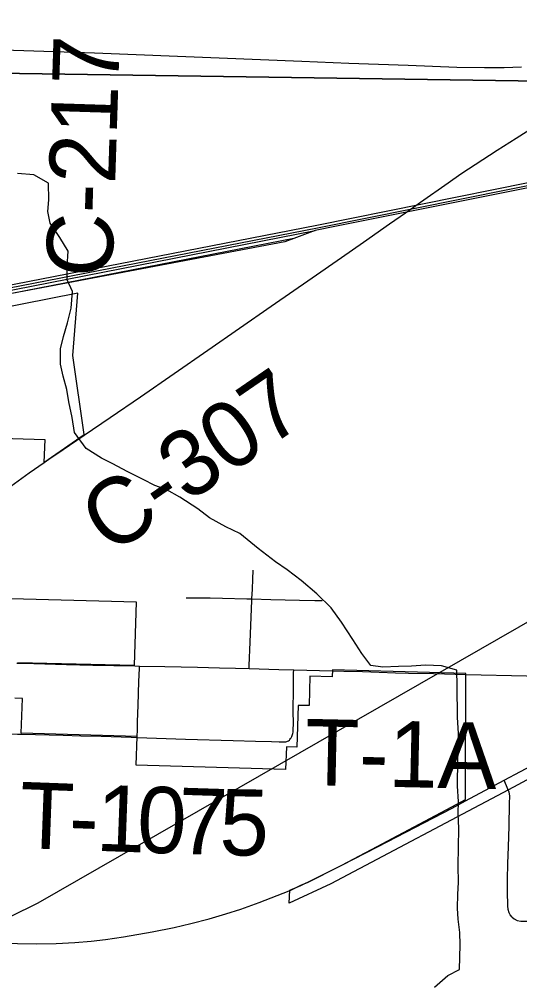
# Model space of a CAD drawing. Extents: x 0 to 34, y 0 to 22.
# Drawn here: x 7.754 to 8.183, y 17.768 to 18.594 of the extents above; entities that cross this region are included whole.
import ezdxf

# ---------------------------------------------------------------- set-up
doc = ezdxf.new("R2010")
doc.units = 0
for name, color, linetype in [('GM_X_City_Street', 7, 'Continuous'), ('GM_X_Corporation', 7, 'Continuous'), ('GM_X_County_Road', 7, 'Continuous'), ('GM_X_County_Road_Text', 7, 'Continuous'), ('GM_X_Minor_River', 7, 'Continuous'), ('GM_X_Rail_Line', 7, 'Continuous'), ('GM_X_State_Route', 7, 'Continuous'), ('GM_X_Township_Road', 7, 'Continuous'), ('GM_X_Township_Road_Text', 7, 'Continuous'), ('GM_X_US_Route', 7, 'Continuous')]:
    doc.layers.add(name, color=color, linetype=linetype)

msp = doc.modelspace()

# ---------------------------------------------------------------- linework, layer by layer
at = {"layer": 'GM_X_City_Street'}
for points in [[(8.17665, 17.82278), (8.175, 17.82467), (8.17417, 17.82649), (8.17328, 17.82943), (8.17286, 17.8325), (8.17261, 17.84493), (8.17277, 17.84885), (8.17272, 17.85509), (8.17305, 17.86874), (8.17364, 17.88324), (8.17404, 17.90092), (8.17452, 17.91992), (8.17459, 17.92691), (8.1741, 17.93021), (8.17311, 17.93259), (8.16992, 17.94028)], [(8.17665, 17.82278), (8.17846, 17.8213), (8.18093, 17.81999), (8.18414, 17.81933), (8.19243, 17.81935), (8.20548, 17.81916), (8.22177, 17.81868), (8.2397, 17.81796), (8.24653, 17.81786), (8.26142, 17.81765), (8.27735, 17.81711), (8.28412, 17.81701)]]:
    msp.add_lwpolyline(points, dxfattribs=at)
at = {"layer": 'GM_X_Corporation'}
for points in [[(8.81843, 19.53953), (8.78463, 18.5318), (7.73457, 18.54715), (7.75042, 19.56547)], [(7.73457, 18.54715), (8.78463, 18.5318), (8.76248, 17.51563), (7.70158, 17.53728)]]:
    msp.add_lwpolyline(points, close=True, dxfattribs=at)
for points in [[(7.72952, 18.23415), (7.77593, 18.23266), (7.7753, 18.21318), (7.80971, 18.23699), (7.8002, 18.30491), (7.8043, 18.35842), (7.73309, 18.34439)], [(7.75292, 18.04149), (7.85301, 18.03916), (7.85462, 18.09328), (7.72505, 18.09663)], [(8.25627, 17.97639), (8.17353, 17.93211), (8.02112, 17.85142), (7.98558, 17.83486), (7.98622, 17.84585), (7.99549, 17.85006), (8.00557, 17.85469), (8.03056, 17.86754), (8.06104, 17.88347), (8.0694, 17.88803), (8.12484, 17.91745), (8.13672, 17.92378), (8.1371, 18.03187), (8.0227, 18.03496), (8.0225, 18.02919), (8.00328, 18.02972), (8.00277, 18.00436), (7.99322, 18.0046), (7.99199, 17.96865), (7.98336, 17.96891), (7.98234, 17.94961), (7.85446, 17.95315), (7.85528, 17.97775), (7.75587, 17.98058), (7.75702, 18.0106), (7.75033, 18.01077)]]:
    msp.add_lwpolyline(points, dxfattribs=at)
at = {"layer": 'GM_X_County_Road'}
for points in [[(7.80968, 18.23644), (7.83193, 18.25162), (7.85806, 18.2695), (7.91568, 18.30933), (7.97021, 18.34722), (8.00531, 18.37164), (8.03029, 18.3891), (8.04915, 18.40224), (8.07165, 18.41777), (8.08512, 18.42737), (8.0981, 18.43647), (8.1218, 18.45322), (8.13259, 18.46075), (8.16384, 18.48102), (8.18012, 18.49132), (8.22474, 18.51963)], [(7.77535, 18.21307), (7.77961, 18.21601), (7.78539, 18.21979), (7.80968, 18.23644)], [(7.72746, 18.17818), (7.73532, 18.18458), (7.74053, 18.18862), (7.74682, 18.19275), (7.76253, 18.20406), (7.77535, 18.21307)]]:
    msp.add_lwpolyline(points, dxfattribs=at)
at = {"layer": 'GM_X_Minor_River'}
for points in [[(8.11616, 18.03838), (8.10252, 18.03903), (8.09037, 18.03812), (8.07937, 18.03796), (8.06571, 18.03746), (8.05549, 18.0388), (8.04773, 18.0492), (8.04, 18.06111), (8.03043, 18.0761), (8.02156, 18.08841), (8.00928, 18.10042), (7.99585, 18.11168), (7.98389, 18.12102), (7.97378, 18.12767), (7.95884, 18.13935), (7.94316, 18.15217), (7.93113, 18.15772), (7.91725, 18.16558), (7.90717, 18.17336), (7.8918, 18.18315), (7.88055, 18.18944), (7.87039, 18.19343), (7.86025, 18.19856), (7.84673, 18.20528), (7.83434, 18.21197), (7.82458, 18.21671), (7.81146, 18.22494), (7.80149, 18.23879), (7.79946, 18.25173), (7.79669, 18.26507), (7.795, 18.27573), (7.79181, 18.28718), (7.78935, 18.29747), (7.78961, 18.31075), (7.79209, 18.32133), (7.79535, 18.33303), (7.79862, 18.34549), (7.79966, 18.3599), (7.7953, 18.36985), (7.79514, 18.38124), (7.79615, 18.3945), (7.78879, 18.40603), (7.78069, 18.41833), (7.77861, 18.42862), (7.77956, 18.43847), (7.77908, 18.4529), (7.7667, 18.45997), (7.75269, 18.461)], [(8.11007, 17.76259), (8.12165, 17.77261), (8.1316, 17.77773), (8.13202, 17.79898), (8.13184, 17.80961), (8.13054, 17.82102), (8.12997, 17.83052), (8.1302, 17.84266), (8.13077, 17.85252), (8.13029, 17.86695), (8.13091, 17.89881), (8.1304, 17.91173), (8.1306, 17.92197), (8.12972, 17.93527), (8.13016, 17.95841), (8.13073, 17.96827), (8.1306, 17.9808), (8.12971, 17.9941), (8.12948, 18.02143), (8.12936, 18.03471), (8.11616, 18.03838)]]:
    msp.add_lwpolyline(points, dxfattribs=at)
at = {"layer": 'GM_X_Rail_Line'}
for p, q in [((6.67145, 18.1505), (8.00771, 18.41211)), ((7.98948, 18.40532), (7.74784, 18.35813)), ((8.00771, 18.41211), (7.98948, 18.40532))]:
    msp.add_line(p, q, dxfattribs=at)
for points in [[(2.1, 17.25784), (2.18393, 17.27433), (2.73729, 17.38072), (3.32149, 17.49791), (3.96117, 17.62281), (4.55539, 17.74), (5.15654, 17.85642), (5.77541, 17.979), (6.33417, 18.09079), (6.90219, 18.20181), (7.3492, 18.28816), (7.42386, 18.30272), (8.00923, 18.41684), (8.46231, 18.50822), (8.9, 18.59581)], [(2.1, 17.25547), (2.18438, 17.27205), (2.73774, 17.37844), (3.32194, 17.49563), (3.96162, 17.62053), (4.55584, 17.73772), (5.15699, 17.85414), (5.77586, 17.97672), (6.33462, 18.08851), (6.90263, 18.19953), (7.34964, 18.28588), (7.42431, 18.30044), (8.00968, 18.41456), (8.46244, 18.50563), (8.9, 18.59339)], [(8.47427, 18.508), (8.37961, 18.48627), (8.21891, 18.45464), (8.02601, 18.41581), (8.00771, 18.41211)], [(7.41313, 17.80694), (7.67204, 17.79992), (7.72265, 17.8116), (7.77034, 17.83497), (8.85455, 18.45807), (8.9, 18.48042)], [(7.98948, 18.40532), (7.9819, 18.4025), (7.74784, 18.35813)]]:
    msp.add_lwpolyline(points, dxfattribs=at)
at = {"layer": 'GM_X_State_Route'}
for points in [[(8.16992, 17.94028), (8.21175, 17.96264), (8.2332, 17.97394), (8.25213, 17.98338), (8.26233, 17.98805), (8.27781, 17.99459), (8.29173, 18.00001), (8.3, 18.00284)], [(8.13675, 17.92262), (8.16186, 17.93597), (8.16992, 17.94028)], [(8.02888, 17.86644), (8.03069, 17.86734), (8.06111, 17.88312), (8.06948, 17.88732), (8.12539, 17.91638), (8.13675, 17.92262)], [(7.98541, 17.84534), (7.98632, 17.8457), (7.9956, 17.85011), (8.00173, 17.85295), (8.02888, 17.86644)], [(7.71558, 17.80075), (7.75263, 17.80005), (7.76913, 17.79996), (7.78565, 17.80022), (7.80173, 17.80104), (7.81591, 17.80224), (7.8282, 17.80367), (7.84352, 17.80594), (7.86797, 17.81012), (7.88681, 17.81386), (7.90128, 17.81723), (7.91683, 17.82138), (7.9311, 17.82556), (7.94405, 17.82978), (7.9598, 17.8354), (7.98541, 17.84534)]]:
    msp.add_lwpolyline(points, dxfattribs=at)
at = {"layer": 'GM_X_Township_Road'}
for p, q in [((7.85308, 18.03844), (7.85717, 18.03836)), ((7.98941, 18.0351), (8.02277, 18.03424))]:
    msp.add_line(p, q, dxfattribs=at)
for points in [[(7.95363, 18.09595), (7.954, 18.10422), (7.95442, 18.113), (7.95476, 18.12075)], [(7.89733, 18.0969), (7.91781, 18.09677), (7.92831, 18.09656), (7.94913, 18.09608), (7.95363, 18.09595)], [(7.95125, 18.03613), (7.95134, 18.03877), (7.95201, 18.05893), (7.95357, 18.09473), (7.95363, 18.09595)], [(7.95363, 18.09595), (7.9697, 18.09552), (7.98205, 18.0953), (7.99433, 18.09497), (8.0075, 18.09473), (8.01381, 18.0947)], [(7.75205, 18.04078), (7.75299, 18.04077), (7.76675, 18.04041), (7.79476, 18.03961), (7.81709, 18.03906), (7.85308, 18.03844)], [(7.85535, 17.97703), (7.85542, 17.98435), (7.85559, 17.99052), (7.85609, 18.00474), (7.85676, 18.02512), (7.8571, 18.03611), (7.85717, 18.03836)], [(7.85717, 18.03836), (7.87902, 18.03795), (7.90689, 18.03723), (7.92584, 18.03677), (7.93959, 18.03646), (7.95125, 18.03613)], [(7.95125, 18.03613), (7.97664, 18.03542), (7.98941, 18.0351)], [(7.98898, 18.00396), (7.98911, 18.01488), (7.98918, 18.02659), (7.98925, 18.02966), (7.98931, 18.03244), (7.98941, 18.0351)], [(8.02277, 18.03424), (8.03244, 18.03398), (8.04831, 18.03357), (8.06261, 18.03303), (8.07671, 18.03264), (8.08781, 18.03233), (8.10931, 18.0318), (8.13717, 18.03115)], [(8.13717, 18.03115), (8.18892, 18.03004), (8.20447, 18.02958), (8.22563, 18.02899), (8.29475, 18.02761), (8.30537, 18.02741), (8.30891, 18.0273), (8.31161, 18.02714), (8.31321, 18.02699), (8.31475, 18.02678), (8.31592, 18.02656), (8.31687, 18.02625), (8.31751, 18.02598), (8.3182, 18.02556), (8.31894, 18.02487), (8.31958, 18.02407), (8.32043, 18.0228), (8.32197, 18.02046), (8.32337, 18.01832), (8.32823, 18.01091)], [(7.98495, 17.9742), (7.9857, 17.97477), (7.98623, 17.97534), (7.98675, 17.97605), (7.98723, 17.97671), (7.98763, 17.97732), (7.98793, 17.97794), (7.9882, 17.9786), (7.98851, 17.97948), (7.98872, 17.9804), (7.9889, 17.98145), (7.98898, 17.98264), (7.98903, 17.98388), (7.98911, 17.98871), (7.98898, 17.99983), (7.98898, 18.00396)], [(7.72142, 17.98039), (7.74189, 17.98014), (7.75251, 17.97991), (7.75594, 17.97986)], [(7.75594, 17.97986), (7.79168, 17.97897), (7.80687, 17.97853), (7.82422, 17.97802), (7.85004, 17.9772), (7.85535, 17.97703)], [(7.85535, 17.97703), (7.89656, 17.97566), (7.93747, 17.97438), (7.9566, 17.97389), (7.9703, 17.97347), (7.97686, 17.97323), (7.97989, 17.97318), (7.98143, 17.97323), (7.98267, 17.97336), (7.98341, 17.97354), (7.9842, 17.9738), (7.98495, 17.9742)]]:
    msp.add_lwpolyline(points, dxfattribs=at)
at = {"layer": 'GM_X_US_Route'}
msp.add_lwpolyline([(7.42128, 18.57924), (7.42674, 18.57898), (7.45222, 18.57817), (7.54914, 18.57442), (7.59699, 18.57256), (7.6299, 18.57117), (7.6852, 18.56899), (7.74048, 18.56714), (7.81873, 18.56464), (7.92554, 18.56029), (7.99634, 18.55743), (8.03671, 18.55592), (8.08763, 18.55403), (8.12926, 18.55245), (8.1529, 18.55204), (8.1697, 18.55217), (8.18464, 18.55274)], dxfattribs=at)

# ---------------------------------------------------------------- texts
at = {"layer": 'GM_X_County_Road_Text'}
for s, rotation, p in [('C-217', 88.17275, (7.83376, 18.37154)), ('C-307', 34.50839, (7.83271, 18.13257))]:
    msp.add_text(s, height=0.056818, rotation=rotation, dxfattribs=at).set_placement(p)
at = {"layer": 'GM_X_Township_Road_Text'}
for s, height, rotation, p in [('T-1A', 0.056818, 358.74769, (7.99848, 17.93625)), ('T', 0.05682, 357.87597, (7.75351, 17.88221)), ('1', 0.05682, 357.90103, (7.81933, 17.87978)), ('0', 0.05682, 357.9636, (7.85437, 17.87849)), ('7', 0.05682, 358.14482, (7.88955, 17.87724)), ('5', 0.05682, 359.01843, (7.92547, 17.87608)), ('-', 0.05682, 357.88423, (7.79599, 17.88064))]:
    msp.add_text(s, height=height, rotation=rotation, dxfattribs=at).set_placement(p)

doc.saveas('drawing.dxf')
